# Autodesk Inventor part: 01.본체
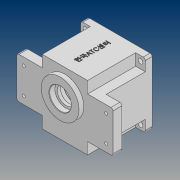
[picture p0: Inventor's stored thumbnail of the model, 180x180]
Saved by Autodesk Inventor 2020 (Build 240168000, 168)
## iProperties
Created: 2020-07
Part Number: 01.본체
Material: 일반
Document SubType Name: Modeling
Designer: PC312-
Density: 1 g/cm^3
Appearance: 기본값
Author: PC312-
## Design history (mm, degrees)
sketch "스케치1"
  geometry: L1 (-47, -47)-(47, -47); L2 (47, -47)-(47, 47); L3 (47, 47)-(-47, 47); L4 (-47, 47)-(-47, -47); L5 (-47, -47)-(47, 47); L6 (47, -47)-(-47, 47); 1 further point
  constraints: 12 end point, 2 midpoint, 2 parallel, 1 horizontal, 1 perpendicular
  dimensions: "d0" = 94 distance of L3.end L2.end; "d1" = 94 distance of L2.end L1.end
extrude "돌출1" new body sketch "스케치1" distance "d2" = 80; taper "d3" = 0 deg
sketch "스케치2"
  geometry: L1 (47, 47)-(-47, 47) reference; L2 (-47, -47)-(47, -47) reference; L3 (-33, 47)-(33, 47); L4 (33, 47)-(33, -47); L5 (33, -47)-(-33, -47); L6 (-33, -47)-(-33, 47); L7 (-47, 47)-(-47, -47) reference; L8 (47, -47)-(47, 47) reference; L9 (-47, 30)-(47, 30); L10 (47, 30)-(47, -30); L11 (47, -30)-(-47, -30); L12 (-47, -30)-(-47, 30); L13 (47, -47)-(47, 47) reference; L14 (33, 47)-(47, 47); 6 further points
  constraints: 18 end point, 4 parallel, 4 point on line, 3 horizontal, 2 perpendicular
  dimensions: "d4" = 33 distance from line of point (0, 0) L4; "d5" = 33 distance from line of point (0, 0) L6; "d6" = 30 distance from line of point (0, 0) L9; "d7" = 30 distance from line of point (0, 0) L11
extrude "돌출2" cut sketch "스케치2" distance "d8" = 70; taper "d9" = 0 deg
sketch "스케치3"
  geometry: L1 (47, -47)-(47, 47) reference; L2 (47, 47)-(33, 47); L3 (33, 47)-(33, 30); L4 (33, 30)-(47, 30); L5 (47, 30)-(47, 47); 2 further points
  constraints: 8 end point, 2 parallel, 1 horizontal, 1 perpendicular
  dimensions: "d10" = 30 distance from line of point (0, 0) L4; "d11" = 33 distance from line of point (0, 0) L3
extrude "돌출3" cut sketch "스케치3" distance "d12" = 70; taper "d13" = 0 deg
sketch "스케치4"
  geometry: L1 (-70, -30)-(70, -30); L2 (70, -30)-(70, 30); L3 (70, 30)-(-70, 30); L4 (-70, 30)-(-70, -30); L5 (-70, -30)-(70, 30); L6 (70, -30)-(-70, 30); 1 further point
  constraints: 12 end point, 2 midpoint, 2 parallel, 1 horizontal, 1 perpendicular
  dimensions: "d14" = 140 distance of L3.end L2.end; "d15" = 60 distance of L2.end L1.end
extrude "돌출4" join sketch "스케치4" distance "d16" = 13; taper "d17" = 0 deg
sketch "스케치5"
  geometry: C1 r 3.5 at (40, 40); 1 further point
  constraints: 1 centre point
  dimensions: "d18" = 7 diameter of C1; "d19" = 40 horizontal distance of point (0, 0) C1.centre; "d20" = 40 horizontal distance of point (0, 0) C1.centre
extrude "돌출5" cut sketch "스케치5" distance "d21" = 70; taper "d22" = 0 deg
sketch "스케치6"
  geometry: 3 further points
  dimensions: "d23" = 60 horizontal distance of point (0, 0) point (60, 19); "d24" = 19 vertical distance of point (0, 0) point (60, 19); "d25" = 60 horizontal distance of point (0, 0) point (60, -19); "d26" = 19 vertical distance of point (0, 0) point (60, -19)
hole "구멍1" sketch "스케치6" at (60, 19), (60, -19) diameter "d27" = 4.5; stored, may be unused: countersink angle "d31" = 90 deg, drill point angle "d33" = 118 deg; dims "d28" = 8, "d29" = 10, "d30" = 5, "d32" = 10
sketch "스케치7"
  geometry: C1 r 27.5 at (0, 11); 1 further point
  constraints: 1 centre point, 1 vertical alignment
  dimensions: "d34" = 55 diameter of C1; "d35" = 11 distance of point (0, 0) C1.centre
extrude "돌출6" join sketch "스케치7" distance "d36" = 7; taper "d37" = 0 deg
sketch "스케치8"
  geometry: C1 r 43 at (0, 0); 1 further point
  constraints: 1 centre point, 1 coincident
  dimensions: "d38" = 86 diameter of C1
extrude "돌출7" cut sketch "스케치8" distance "d39" = 9; taper "d40" = 0 deg
sketch "스케치9"
  geometry: C1 r 40 at (0, 0); 1 further point
  constraints: 1 centre point, 1 coincident
  dimensions: "d41" = 80 diameter of C1
extrude "돌출8" cut sketch "스케치9" distance "d42" = 62; taper "d43" = 0 deg
sketch "스케치10"
  geometry: C1 r 27.5 at (0, 11) reference; A1 r 21 centre (0, 11) between (8.978, -7.984) and (-8.978, -7.984); A2 r 15 centre (0, -20) between (-8.978, -7.984) and (8.978, -7.984); 1 further point
  constraints: 4 point on circle, 2 centre point, 1 coincident, 1 vertical alignment
  dimensions: "d44" = 42 diameter of A1; "d45" = 30 diameter of A2; "d46" = 20 distance of A2.centre point (0, 0)
extrude "돌출9" join sketch "스케치10" distance "d47" = 7; taper "d48" = 0 deg
sketch "스케치11"
  geometry: C1 r 12.5 at (0, 11); A1 r 21 centre (0, 11) between (8.978, -7.984) and (-8.978, -7.984) reference; 1 further point
  constraints: 1 centre point, 1 coincident
  dimensions: "d49" = 25 diameter of C1
extrude "돌출10" cut sketch "스케치11" extent not by distance; stored distance "d50" = 0; taper "d51" = 0 deg
sketch "스케치12"
  geometry: C1 r 12.5 at (0, 11) reference; C2 r 17.5 at (0, 11); 1 further point
  constraints: 1 centre point, 1 coincident
  dimensions: "d52" = 35 diameter of C2
extrude "돌출11" cut sketch "스케치12" distance "d53" = 10; taper "d54" = 0 deg
sketch "스케치13"
  geometry: C1 r 27.5 at (0, 0) reference; C2 r 16 at (0, 0); 1 further point
  constraints: 1 centre point, 1 coincident
  dimensions: "d55" = 32 diameter of C2
extrude "돌출12" cut sketch "스케치13" distance "d56" = 8.3; taper "d57" = 0 deg
chamfer "모따기2" distance "d61" = 1; stored, may be unused: second distance "d62" = 2, angle "d63" = 45 deg
sketch "스케치14"
  geometry: C1 r 11 at (0, -20); A1 r 15 centre (0, -20) between (-8.978, -7.984) and (8.978, -7.984) reference; 1 further point
  constraints: 1 centre point, 1 coincident
  dimensions: "d64" = 22 diameter of C1
extrude "돌출13" cut sketch "스케치14" distance "d65" = 7; taper "d66" = 0 deg
sketch "스케치15"
  geometry: C1 r 11 at (0, 0) reference; C2 r 9.5 at (0, 0); 1 further point
  constraints: 1 centre point, 1 coincident
  dimensions: "d67" = 19 diameter of C2
extrude "돌출14" cut sketch "스케치15" distance "d68" = 3; taper "d69" = 0 deg
fillet "모깎기1" dims "d70" = 3
chamfer "모따기3" distance "d71" = 1; stored, may be unused: second distance "d72" = 2, angle "d73" = 45 deg
sketch "스케치19" dims "d90" = 72
  geometry: L1 (-98, 0)-(98, 0) reference; L2 (-36, 4)-(-39.799, 4); L3 (-36, -4)-(-39.799, -4); A1 r 4 centre (-36, 0) between (-36, 4) and (-36, -4); A2 r 40 centre (0, 0) between (-39.799, 4) and (-39.799, -4) reference; 2 further points
  constraints: 4 end point, 4 point on circle, 2 tangent, 1 centre point, 1 coincident, 1 horizontal, 1 horizontal alignment, 1 parallel, 1 point on line, 2 other
  dimensions: "d91" = 8 diameter of A1
extrude "돌출17" join sketch "스케치19" stored distance "d92" = 3; taper "d93" = 0 deg
fillet "모깎기2" dims "d94" = 3
sketch "스케치20"
  geometry: A1 r 4 centre (-36, 0) between (-36, -4) and (-36, 4) reference; 2 further points
  constraints: 1 coincident
hole "구멍3" sketch "스케치20" at (-36, 0) diameter "d95" = 3.242; stored, may be unused: countersink angle "d99" = 90 deg, drill point angle "d101" = 118 deg; dims "d96" = 7, "d97" = 10, "d98" = 5, "d100" = 9
fillet "모깎기3" dims "d102" = 3
fillet "모깎기4" dims "d103" = 3
node "작업 평면1"
sketch "스케치21"
  geometry: L1 (77, 80)-(-11, 80) reference; 2 further points
  constraints: 1 vertical alignment, 1 other
  dimensions: "d105" = 40 distance from line of L1 point (33, 40)
feature "엠보싱1" sketch "스케치21" dims "d6" = 30, "d7" = 30, "d106" = 0.5, "d107" = 0
chamfer "모따기4" distance "d108" = 0.8; stored, may be unused: second distance "d109" = 2, angle "d110" = 30 deg
chamfer "모따기5" distance "d111" = 1; stored, may be unused: second distance "d112" = 2, angle "d113" = 30 deg
node "솔리드1"
mirror "미러1"
mirror "미러2"
mirror "미러3"
mirror "미러4"
node "투영된 루프1"
feature "A9D066F2-1C7D-4E18-AEED-F7BC21143FA4" dims "d27" = 4.5, "d28" = 8, "d29" = 10, "d30" = 5, "d31" = 90 deg, "d32" = 10, "d33" = 118 deg
